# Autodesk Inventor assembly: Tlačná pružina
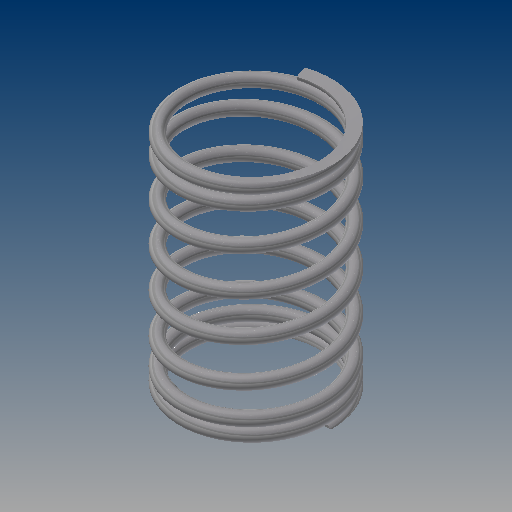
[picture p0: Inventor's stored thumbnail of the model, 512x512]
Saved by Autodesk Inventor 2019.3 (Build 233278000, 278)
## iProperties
ClientObjectVersion: 1
Created: 2019-05
Part Number: Tlačná pružina
Document SubType Name: Assembly
Designer: B-hon
Author: B-hon
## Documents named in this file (2)
- C:\Users\B-hon\OneDrive\Plocha\Bakalářka22\Přítlak spodní\Levý\Přítlak3s\Design Accelerator\Tlačná pružina3.iam
- C:\Users\B-hon\OneDrive\Plocha\Bakalářka22\Přítlak spodní\Levý\Přítlak3s\Design Accelerator\Tlačná pružina13.ipt
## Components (1 placed, 1 different names)
1. Tlačná pružina1:1
